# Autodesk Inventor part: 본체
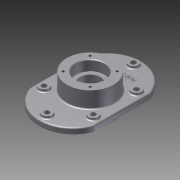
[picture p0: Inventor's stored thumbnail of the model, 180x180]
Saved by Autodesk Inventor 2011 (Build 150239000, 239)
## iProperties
Created: 2015-02
Part Number: 본체
Document SubType Name: Modeling
Designer: Administrator
Density: 2.71 g/cm^3
Material: 알루미늄-6061
Mass: 1637.12 g
Surface Area: 925.884 cm^2
Volume: 604.103 cm^3
Author: Administrator
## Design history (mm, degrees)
sketch "스케치1"
  geometry: L1 (-70, 60)-(70, 60); L2 (70, 60)-(70, -60); L3 (70, -60)-(-70, -60); L4 (-70, -60)-(-70, 60); L5 (0, 60)-(0, 110); L6 (0, -60)-(0, -110); A1 r 74 centre (0, 36) between (70, 60) and (-70, 60); A2 r 74 centre (0, -36) between (-70, -60) and (70, -60); 3 further points
  constraints: 12 end point, 6 point on circle, 3 midpoint, 2 centre point, 1 coincident, 1 horizontal alignment, 1 vertical alignment
  dimensions: "d1" = 140 distance of L1.start L1.end; "d2" = 120 distance of L3.end L1.start; "d3" = 50 distance of L5.start L5.end; "d4" = 50 distance of L6.start L6.end; "d5" = 220 distance of L6.end L5.end
extrude "돌출1" new body sketch "스케치1" distance "d6" = 12; taper "d7" = 0 deg
sketch "스케치2"
  geometry: C1 r 50 at (0, 0); 1 further point
  constraints: 1 centre point, 1 coincident
  dimensions: "d8" = 100 diameter of C1
extrude "돌출2" join sketch "스케치2" distance "d9" = 35; taper "d10" = 0 deg
sketch "스케치3"
  geometry: C1 r 50 at (0, 0); 1 further point
  constraints: 1 centre point, 1 coincident
  dimensions: "d11" = 100 diameter of C1
extrude "돌출3" join sketch "스케치3" distance "d12" = 23; taper "d13" = 0 deg
sketch "스케치4"
  geometry: C1 r 50 at (0, 0) reference; C2 r 31 at (0, 0)
  constraints: 1 centre point, 1 coincident
  dimensions: "d14" = 62 diameter of C2
extrude "돌출4" cut sketch "스케치4" distance "d15" = 22; taper "d16" = 0 deg
sketch "스케치5"
  geometry: C1 r 50 at (0, 0) reference; C2 r 31 at (0, 0)
  constraints: 1 centre point, 1 coincident
  dimensions: "d17" = 62 diameter of C2
extrude "돌출5" cut sketch "스케치5" distance "d18" = 22; taper "d19" = 0 deg
sketch "스케치6"
  geometry: C1 r 31 at (0, 0) reference; C2 r 22.5 at (0, 0)
  constraints: 1 centre point, 1 coincident
  dimensions: "d20" = 45 diameter of C2
extrude "돌출6" cut sketch "스케치6" stored distance "d21" = 22; taper "d22" = 0 deg
sketch "스케치7"
  geometry: L1 (0, 0)-(0, 41); L2 (0, 0)-(28.991, 28.991); C1 r 50 at (0, 0) reference; A1 r 41 centre (0, 0) between (0, 41) and (28.991, 28.991); 1 further point
  constraints: 4 end point, 2 coincident, 2 point on circle, 1 centre point, 1 vertical
  dimensions: "d23" = 82 diameter of A1; "d24" = 45 deg angle of L2 L1
hole "Hole1" sketch "스케치7" at (28.991, 28.991) diameter "d25" = 4.917; stored, may be unused: countersink angle "d29" = 90 deg, drill point angle "d31" = 118 deg; dims "d26" = 10, "d27" = 4, "d28" = 2, "d30" = 13
sketch "스케치8"
  geometry: L1 (0, 0)-(28.991, 28.991); L2 (0, 41)-(0, 0); C1 r 31 at (0, 0) reference; C2 r 50 at (0, 0) reference; A1 r 41 centre (0, 0) between (28.991, 28.991) and (0, 41); 1 further point
  constraints: 4 end point, 3 coincident, 2 point on circle, 1 centre point, 1 vertical
  dimensions: "d35" = 82 diameter of A1; "d36" = 45 deg angle of L1 L2
hole "Hole2" sketch "스케치8" at (28.991, 28.991) diameter "d37" = 4.917; stored, may be unused: countersink angle "d41" = 90 deg, drill point angle "d43" = 118 deg; dims "d38" = 10, "d39" = 4, "d40" = 2, "d42" = 13
sketch "스케치9"
  geometry: L1 (-70, -60)-(-70, 60) reference; L2 (70, 60)-(70, -60) reference; L3 (-53, 60)-(-53, -60); L4 (53, 60)-(53, -60); L5 (0, -110)-(0, -93); L6 (0, 110)-(0, 93); L7 (-80.54, 46.5)-(-53, 46.5); L8 (-80.54, -46.5)-(-53, -46.5); L9 (80.54, 46.5)-(53, 46.5); L10 (80.54, -46.5)-(53, -46.5); C1 r 50 at (0, 0) reference; C2 r 10 at (0, 93); C3 r 10 at (0, -93); C4 r 10 at (-80.54, 46.5); C5 r 10 at (-80.54, -46.5); C6 r 10 at (0, -93); C7 r 10 at (80.54, -46.5); C8 r 10 at (80.54, 46.5); C9 r 10 at (-53, 46.5); C10 r 10 at (-53, -46.5); C11 r 10 at (53, 46.5); C12 r 10 at (53, -46.5); A1 r 74 centre (0, 36) between (70, 60) and (-70, 60) reference; A2 r 74 centre (0, -36) between (-70, -60) and (70, -60) reference; A3 r 59.061 centre (0, 33.939) between (53, 60) and (-53, 60); A4 r 59.061 centre (0, -33.939) between (-53, -60) and (53, -60); 2 further points
  constraints: 16 end point, 13 centre point, 8 point on circle, 6 coincident, 4 point on line, 2 horizontal alignment, 2 midpoint, 1 vertical, 13 other
  dimensions: "d47" = 120 distance of L3.start L3.end; "d48" = 17 distance between parallel lines of L3 L1; "d49" = 17 distance between parallel lines of L2 L4; "d50" = 120 distance of L4.start L4.end; "d51" = 17 distance of L5.start L5.end; "d52" = 17 distance of L6.start L6.end; "d53" = 20 diameter of C2; "d54" = 20 diameter of C3; "d57" = 360 deg dimension on C1.centre C2.centre (derived); "d59" = 20 diameter of C9; "d60" = 20 diameter of C11; "d61" = 20 diameter of C10; "d63" = 20 diameter of C12
extrude "돌출7" join sketch "스케치9" distance "d64" = 5; taper "d65" = 0 deg
sketch "스케치10"
  geometry: C1 r 10 at (0, 0) reference; C2 r 10 at (-53, -46.5) reference; C3 r 10 at (-53, -139.5) reference; C4 r 10 at (0, -186) reference; C5 r 10 at (53, -139.5) reference; C6 r 10 at (53, -46.5) reference; 7 further points
  constraints: 6 coincident
hole "Hole3" sketch "스케치10" at (0, 0), (-53, -46.5), (-53, -139.5), (0, -186), (53, -139.5), (53, -46.5) diameter "d66" = 11; stored, may be unused: countersink angle "d70" = 90 deg, drill point angle "d72" = 118 deg; dims "d67" = 10, "d68" = 4, "d69" = 2, "d71" = 13
fillet "모깎기1" dims "d73" = 0.3
chamfer "모따기1" distance "d74" = 1; stored, may be unused: second distance "d75" = 2, angle "d76" = 45 deg
fillet "모깎기3" dims "d78" = 3
sketch "스케치11"
  geometry: L1 (-33.101, 69.803)-(33.101, 69.803); L2 (33.101, 69.803)-(33.101, 60.197); L3 (33.101, 60.197)-(-33.101, 60.197); L4 (-33.101, 60.197)-(-33.101, 69.803); L5 (-33.101, 65)-(33.101, 65); C1 r 53 at (0, 0) reference; 2 further points
  constraints: 3 midpoint, 2 end point, 2 vertical alignment, 2 other
  dimensions: "d79" = 65 vertical distance of C1.centre L5.start
feature "엠보싱1" sketch "스케치11" dims "d1" = 140, "d80" = 1, "d81" = 0
fillet "모깎기4" dims "d82" = 3
node "솔리드1"
pattern_circular "원형 패턴1" dims angle "d33" = 360 deg
pattern_circular "원형 패턴2" dims angle "d45" = 360 deg
node "투영된 루프1"
node "투영된 루프2"
node "투영된 루프3"
node "투영된 루프4"
